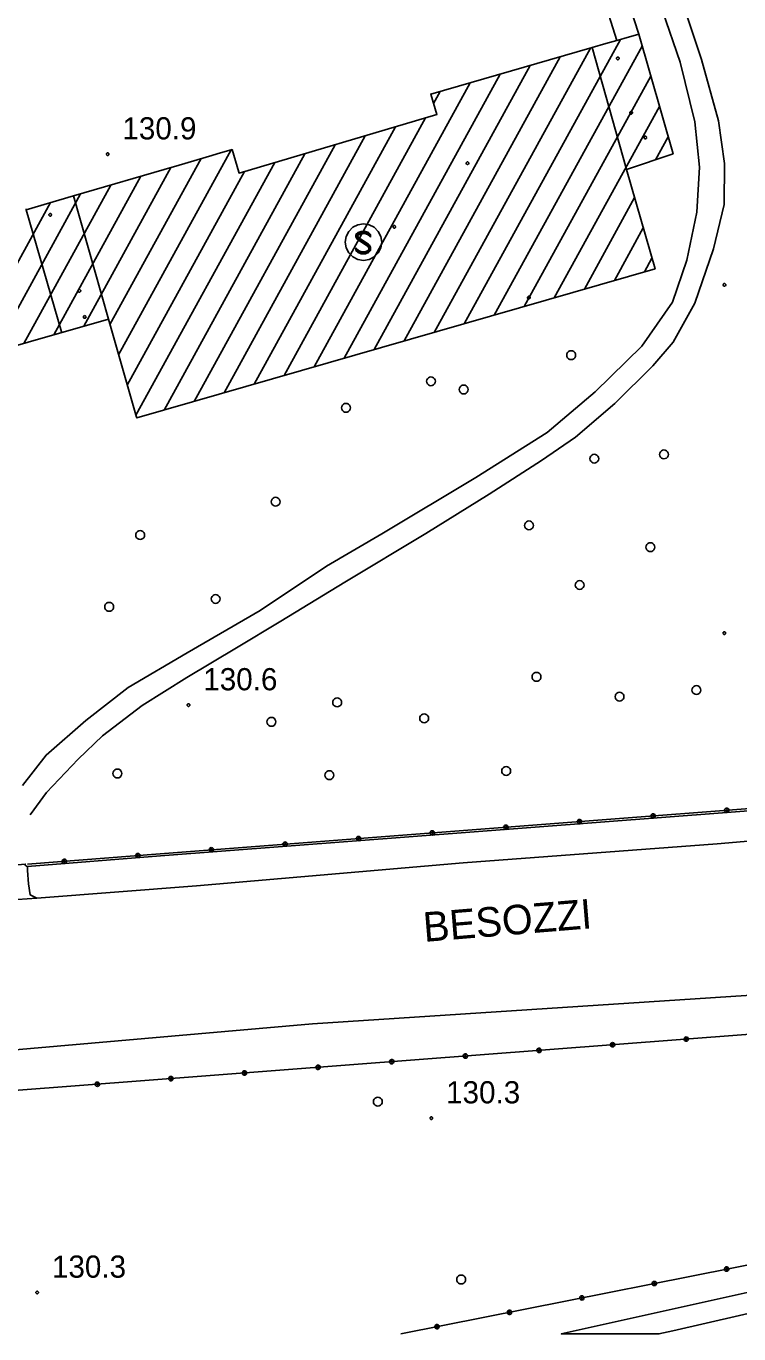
# Model space of a CAD drawing. Extents: x 513373 to 514978, y 5038576 to 5040180.
# Drawn here: x 513502.4 to 513550.7, y 5038580.1 to 5038668.6 of the extents above; entities that cross this region are included whole.
import ezdxf

# ---------------------------------------------------------------- set-up
doc = ezdxf.new("R2010")
doc.units = 0
for name, color, linetype in [('2010300', 7, 'Continuous'), ('3010204', 7, 'Continuous'), ('3030201', 7, 'Continuous'), ('B1211', 7, 'Continuous'), ('C1131', 7, 'Continuous'), ('C12211', 7, 'Continuous'), ('C2911', 7, 'Continuous'), ('CAMP_C12211', 7, 'Continuous'), ('Default', 7, 'Continuous'), ('F12107', 7, 'Continuous'), ('F12131', 7, 'Continuous'), ('F12132', 7, 'Continuous'), ('G4315', 7, 'Continuous'), ('TOP500', 7, 'Continuous'), ('TOP920', 7, 'Continuous')]:
    doc.layers.add(name, color=color, linetype=linetype)

# ---------------------------------------------------------------- blocks, each defined once
blk = doc.blocks.new('CAMP_2F84D089')
at = {"layer": 'CAMP_C12211'}
for p, q in [((49.808, -7.618), (60.382, 11.617)), ((47.775, -8.202), (58.347, 11.029)), ((51.841, -7.034), (61.849, 11.171)), ((43.709, -9.371), (54.279, 9.856)), ((45.742, -8.787), (56.313, 10.442)), ((41.676, -9.955), (52.245, 9.269)), ((53.874, -6.45), (62.437, 9.127)), ((39.643, -10.54), (50.21, 8.682)), ((47.729, 7.282), (48.176, 8.095)), ((55.907, -5.865), (63.024, 7.082)), ((37.61, -11.124), (47.19, 6.302)), ((35.577, -11.708), (45.146, 5.698)), ((31.511, -12.877), (41.059, 4.491)), ((33.544, -12.293), (43.103, 5.094)), ((62.756, 3.48), (63.612, 5.037)), ((25.809, -7.68), (31.984, 3.551)), ((26.397, -9.725), (34.023, 4.147)), ((29.478, -13.461), (39.015, 3.887)), ((24.042, -7.782), (29.945, 2.956)), ((26.985, -11.769), (34.928, 2.68)), ((27.573, -13.814), (36.972, 3.283)), ((22.009, -8.366), (27.906, 2.36)), ((17.943, -9.535), (23.827, 1.168)), ((19.976, -8.95), (25.866, 1.764)), ((57.94, -5.281), (61.345, 0.913)), ((15.91, -10.119), (21.788, 0.573)), ((59.973, -4.697), (61.932, -1.132)), ((62.005, -4.112), (62.519, -3.177))]:
    blk.add_line(p, q, dxfattribs=at)
blk = doc.blocks.new('03080200')
at = {"layer": 'Default'}
for p, q in [((-0.139, 0.046), (-0.146, 0)), ((-0.146, 0), (-0.139, -0.046)), ((-0.118, 0.086), (-0.139, 0.046)), ((-0.086, 0.118), (-0.118, 0.086)), ((-0.046, 0.139), (-0.086, 0.118)), ((0, 0.146), (-0.046, 0.139)), ((-0.042, 0.014), (-0.045, 0)), ((-0.045, 0), (-0.042, -0.014)), ((-0.036, 0.026), (-0.042, 0.014)), ((-0.026, 0.036), (-0.036, 0.026)), ((-0.014, 0.042), (-0.026, 0.036)), ((0, 0.045), (-0.014, 0.042)), ((0.046, 0.139), (0, 0.146)), ((0.014, 0.042), (0, 0.045)), ((0.026, 0.036), (0.014, 0.042)), ((0.036, 0.026), (0.026, 0.036)), ((0.042, 0.014), (0.036, 0.026)), ((0.045, 0), (0.042, 0.014)), ((0.042, -0.014), (0.045, 0)), ((0.086, 0.118), (0.046, 0.139)), ((0.118, 0.086), (0.086, 0.118)), ((0.139, 0.046), (0.118, 0.086)), ((0.146, 0), (0.139, 0.046)), ((0.139, -0.046), (0.146, 0)), ((-0.139, -0.046), (-0.118, -0.086)), ((-0.118, -0.086), (-0.086, -0.118)), ((-0.086, -0.118), (-0.046, -0.139)), ((-0.046, -0.139), (0, -0.146)), ((-0.042, -0.014), (-0.036, -0.026)), ((-0.036, -0.026), (-0.026, -0.036)), ((-0.026, -0.036), (-0.014, -0.042)), ((-0.014, -0.042), (0, -0.045)), ((0, -0.045), (0.014, -0.042)), ((0, -0.146), (0.046, -0.139)), ((0.014, -0.042), (0.026, -0.036)), ((0.026, -0.036), (0.036, -0.026)), ((0.036, -0.026), (0.042, -0.014)), ((0.046, -0.139), (0.086, -0.118)), ((0.086, -0.118), (0.118, -0.086)), ((0.118, -0.086), (0.139, -0.046))]:
    blk.add_line(p, q, dxfattribs=at)
blk = doc.blocks.new('08020400')
at = {"layer": 'Default'}
for p, q in [((-0.086, 0.028), (-0.09, 0)), ((-0.09, 0), (-0.086, -0.028)), ((-0.073, 0.053), (-0.086, 0.028)), ((-0.053, 0.073), (-0.073, 0.053)), ((-0.028, 0.086), (-0.053, 0.073)), ((0, 0.09), (-0.028, 0.086)), ((0.028, 0.086), (0, 0.09)), ((0.053, 0.073), (0.028, 0.086)), ((0.073, 0.053), (0.053, 0.073)), ((0.086, 0.028), (0.073, 0.053)), ((0.09, 0), (0.086, 0.028)), ((0.086, -0.028), (0.09, 0)), ((-0.086, -0.028), (-0.073, -0.053)), ((-0.073, -0.053), (-0.053, -0.073)), ((-0.053, -0.073), (-0.028, -0.086)), ((-0.028, -0.086), (0, -0.09)), ((0, -0.09), (0.028, -0.086)), ((0.028, -0.086), (0.053, -0.073)), ((0.053, -0.073), (0.073, -0.053)), ((0.073, -0.053), (0.086, -0.028))]:
    blk.add_line(p, q, dxfattribs=at)
blk = doc.blocks.new('NSIMB25')
at = {"layer": 'Default'}
for p, q in [((-0.086, 0.028), (-0.09, 0)), ((-0.09, 0), (-0.086, -0.028)), ((-0.073, 0.053), (-0.086, 0.028)), ((-0.053, 0.073), (-0.073, 0.053)), ((-0.028, 0.086), (-0.053, 0.073)), ((0, 0.09), (-0.028, 0.086)), ((0.028, 0.086), (0, 0.09)), ((0.053, 0.073), (0.028, 0.086)), ((0.073, 0.053), (0.053, 0.073)), ((0.086, 0.028), (0.073, 0.053)), ((0.09, 0), (0.086, 0.028)), ((0.086, -0.028), (0.09, 0)), ((-0.086, -0.028), (-0.073, -0.053)), ((-0.073, -0.053), (-0.053, -0.073)), ((-0.053, -0.073), (-0.028, -0.086)), ((-0.028, -0.086), (0, -0.09)), ((0, -0.09), (0.028, -0.086)), ((0.028, -0.086), (0.053, -0.073)), ((0.053, -0.073), (0.073, -0.053)), ((0.073, -0.053), (0.086, -0.028))]:
    blk.add_line(p, q, dxfattribs=at)
blk = doc.blocks.new('05010100')
at = {"layer": 'Default'}
for p, q in [((-0.143, 0.046), (-0.15, 0)), ((-0.15, 0), (-0.143, -0.046)), ((-0.121, 0.088), (-0.143, 0.046)), ((-0.088, 0.121), (-0.121, 0.088)), ((-0.046, 0.143), (-0.088, 0.121)), ((0, 0.15), (-0.046, 0.143)), ((0.046, 0.143), (0, 0.15)), ((0.088, 0.121), (0.046, 0.143)), ((0.121, 0.088), (0.088, 0.121)), ((0.143, 0.046), (0.121, 0.088)), ((0.15, 0), (0.143, 0.046)), ((0.143, -0.046), (0.15, 0)), ((-0.143, -0.046), (-0.121, -0.088)), ((-0.121, -0.088), (-0.088, -0.121)), ((-0.088, -0.121), (-0.046, -0.143)), ((-0.046, -0.143), (0, -0.15)), ((0, -0.15), (0.046, -0.143)), ((0.046, -0.143), (0.088, -0.121)), ((0.088, -0.121), (0.121, -0.088)), ((0.121, -0.088), (0.143, -0.046))]:
    blk.add_line(p, q, dxfattribs=at)
blk = doc.blocks.new('03030201')
at = {"layer": 'Default'}
for p, q in [((-0.728, 1.001), (-1.001, 0.728)), ((-0.382, 1.177), (-0.728, 1.001)), ((0, 1.237), (-0.382, 1.177)), ((0.382, 1.177), (0, 1.237)), ((0.728, 1.001), (0.382, 1.177)), ((1.001, 0.728), (0.728, 1.001)), ((-1.177, 0.382), (-1.238, 0)), ((-1.238, 0), (-1.177, -0.382)), ((-1.001, 0.728), (-1.177, 0.382)), ((-0.518, 0.508), (-0.368, 0.643)), ((-0.518, 0.358), (-0.518, 0.508)), ((-0.443, 0.223), (-0.518, 0.358)), ((-0.333, 0.584), (-0.451, 0.478)), ((-0.451, 0.478), (-0.451, 0.376)), ((-0.451, 0.376), (-0.389, 0.265)), ((-0.368, 0.148), (-0.443, 0.223)), ((-0.389, 0.265), (-0.326, 0.201)), ((-0.298, 0.526), (-0.383, 0.448)), ((-0.383, 0.448), (-0.383, 0.394)), ((-0.383, 0.394), (-0.335, 0.306)), ((-0.368, 0.643), (-0.158, 0.718)), ((0.148, -0.186), (-0.368, 0.148)), ((-0.335, 0.306), (-0.287, 0.257)), ((-0.147, 0.651), (-0.333, 0.584)), ((-0.326, 0.201), (0.183, -0.128)), ((-0.135, 0.583), (-0.298, 0.526)), ((-0.287, 0.257), (-0.18, 0.198)), ((-0.18, 0.198), (0.337, -0.137)), ((-0.158, 0.718), (0.127, 0.718)), ((0.115, 0.651), (-0.147, 0.651)), ((0.103, 0.583), (-0.135, 0.583)), ((0.266, 0.526), (0.103, 0.583)), ((0.301, 0.584), (0.115, 0.651)), ((0.127, 0.718), (0.337, 0.643)), ((0.487, 0.327), (0.266, 0.526)), ((0.487, 0.418), (0.301, 0.584)), ((0.337, 0.643), (0.487, 0.508)), ((0.487, 0.508), (0.487, 0.327)), ((1.177, 0.382), (1.001, 0.728)), ((1.238, 0), (1.177, 0.382)), ((1.177, -0.382), (1.238, 0)), ((-1.177, -0.382), (-1.001, -0.728)), ((-1.001, -0.728), (-0.728, -1.001)), ((-0.518, -0.39), (-0.298, -0.588)), ((-0.518, -0.572), (-0.518, -0.39)), ((-0.333, -0.647), (-0.518, -0.481)), ((-0.368, -0.707), (-0.518, -0.572)), ((-0.158, -0.782), (-0.368, -0.707)), ((-0.147, -0.714), (-0.333, -0.647)), ((-0.298, -0.588), (-0.135, -0.647)), ((0.127, -0.782), (-0.158, -0.782)), ((0.115, -0.714), (-0.147, -0.714)), ((-0.135, -0.647), (0.103, -0.647)), ((0.103, -0.647), (0.266, -0.588)), ((0.301, -0.647), (0.115, -0.714)), ((0.337, -0.707), (0.127, -0.782)), ((0.254, -0.245), (0.148, -0.186)), ((0.183, -0.128), (0.295, -0.191)), ((0.302, -0.293), (0.254, -0.245)), ((0.266, -0.588), (0.352, -0.512)), ((0.295, -0.191), (0.357, -0.253)), ((0.419, -0.542), (0.301, -0.647)), ((0.352, -0.382), (0.302, -0.293)), ((0.337, -0.137), (0.412, -0.212)), ((0.487, -0.572), (0.337, -0.707)), ((0.352, -0.512), (0.352, -0.382)), ((0.357, -0.253), (0.419, -0.364)), ((0.412, -0.212), (0.487, -0.347)), ((0.419, -0.364), (0.419, -0.542)), ((0.487, -0.347), (0.487, -0.572)), ((0.728, -1.001), (1.001, -0.728)), ((1.001, -0.728), (1.177, -0.382)), ((-0.728, -1.001), (-0.382, -1.177)), ((-0.382, -1.177), (0, -1.238)), ((0, -1.238), (0.382, -1.177)), ((0.382, -1.177), (0.728, -1.001))]:
    blk.add_line(p, q, dxfattribs=at)
blk = doc.blocks.new('A$C3704598A')
at = {"layer": '2010300'}
blk.add_lwpolyline([(165.65, -800.002), (186.154, -795.446), (186.667, -795.332), (187.178, -795.219)], dxfattribs=at)
at = {"layer": '3010204'}
for points in [[(130.78, -763.373), (132.923, -761.13), (134.586, -759.538), (137.271, -757.48), (140.294, -755.605), (143.656, -753.598), (146.655, -751.79), (150.994, -749.135), (156.469, -745.856), (160.764, -743.2), (164.309, -740.923), (166.605, -739.336), (169.269, -737.051), (171.844, -734.517), (173.213, -732.901), (174.681, -730.267), (175.954, -726.593), (176.68, -723.592), (176.702, -720.811), (176.296, -717.936), (175.153, -713.79), (173.012, -707.42)], [(171.782, -708.472), (172.512, -710.49), (173.705, -713.959), (174.69, -717.991), (175.004, -721.069), (174.821, -724.119), (174.14, -727.369), (173.19, -730.21), (171.108, -733.178), (167.941, -736.272), (164.686, -739.027), (159.868, -742.062), (153.485, -745.877), (149.737, -748.062), (145.259, -751.056), (140.307, -753.932), (136.309, -756.274), (133.443, -758.512), (130.755, -760.841), (129.156, -762.908)], [(168.448, -709.407), (169.416, -712.491)], [(169.896, -709.001), (170.888, -712.066)], [(130.78, -763.373), (129.681, -764.88)]]:
    blk.add_lwpolyline(points, dxfattribs=at)
at = {"layer": 'B1211'}
for points in [[(182.854, -779.395), (110.289, -784.942), (71.944, -788.357), (71.695, -785.89), (71.68, -785.737), (74.707, -785.49), (148.809, -779.036), (181.633, -776.874)], [(190.042, -765.652), (176.206, -766.841), (159.007, -768.13), (140.939, -769.683), (130.118, -770.52), (129.683, -770.31), (129.556, -769.565), (129.505, -768.659), (129.503, -768.536), (129.499, -768.38), (138.496, -767.667), (189.536, -763.755)]]:
    blk.add_lwpolyline(points, dxfattribs=at)
for points in [[(129.499, -768.38), (129.503, -768.536), (129.505, -768.659), (129.556, -769.565), (129.683, -770.31), (130.118, -770.52), (128.815, -770.62), (126.207, -770.822), (126.566, -770.204), (126.591, -769.326), (126.388, -768.62), (126.424, -768.6), (126.448, -768.577), (126.467, -768.547), (126.48, -768.508), (126.48, -768.461), (129.344, -768.218), (129.347, -768.247), (129.349, -768.267), (129.368, -768.312), (129.402, -768.35), (129.432, -768.367), (129.469, -768.378)], [(239.733, -784.162), (238.193, -784.525), (218.713, -789.182), (196.51, -794.439), (195.488, -794.673), (173.196, -799.794), (172.259, -800.002), (165.65, -800.002), (186.154, -795.446), (186.667, -795.332), (187.178, -795.219), (234.926, -783.811), (239.656, -782.696), (240.683, -782.453)]]:
    blk.add_lwpolyline(points, close=True, dxfattribs=at)
at = {"layer": 'C1131'}
for points in [[(170.068, -721.225), (170.039, -721.125), (167.729, -712.978), (168.669, -712.707), (169.408, -712.493), (169.881, -712.357), (170.888, -712.066), (173.213, -720.156)], [(170.068, -721.225), (171.998, -727.944), (136.894, -738.034), (136.879, -737.982), (134.971, -731.345), (132.618, -723.012), (139.462, -721.011), (139.54, -720.988), (140.996, -720.564), (141.976, -720.277), (142.351, -720.168), (143.357, -719.874), (143.81, -721.41), (143.828, -721.469), (157.221, -717.513), (156.812, -716.127), (166.721, -713.269), (167.729, -712.978), (170.039, -721.125)], [(134.971, -731.345), (133.964, -731.634), (131.815, -732.252), (131.8, -732.2), (129.413, -723.947), (131.612, -723.305), (132.618, -723.012)]]:
    blk.add_lwpolyline(points, close=True, dxfattribs=at)
blk.add_lwpolyline([(129.397, -723.891), (129.413, -723.947), (131.8, -732.2), (131.815, -732.252), (122.84, -734.831)], dxfattribs=at)
at = {"layer": 'C12211'}
blk.add_lwpolyline([(129.397, -723.891), (129.413, -723.947), (131.612, -723.305), (132.618, -723.012), (139.462, -721.011), (139.54, -720.988), (140.996, -720.564), (141.976, -720.277), (142.351, -720.168), (143.357, -719.874), (143.81, -721.41), (143.828, -721.469), (157.221, -717.513), (156.812, -716.127), (166.721, -713.269), (167.729, -712.978), (168.669, -712.707), (169.408, -712.493), (169.881, -712.357), (170.888, -712.066), (173.213, -720.156), (170.068, -721.225), (171.998, -727.944), (136.894, -738.034), (136.879, -737.982), (134.971, -731.345), (133.964, -731.634), (131.815, -732.252), (122.84, -734.831)], dxfattribs=at)
at = {"layer": 'C2911'}
for points in [[(129.493, -768.231), (138.486, -767.517), (158.144, -766.013), (189.264, -763.627), (189.631, -763.599), (190.369, -763.543), (197.35, -752.142), (188.981, -734.343), (179.304, -712.974), (176.303, -705.995)], [(71.944, -788.357), (110.289, -784.942), (182.854, -779.395)], [(154.78, -800.002), (185.721, -793.86), (186.751, -793.656)]]:
    blk.add_lwpolyline(points, dxfattribs=at)
at = {"layer": '3030201'}
blk.add_blockref('03030201', (152.25, -726.137), dxfattribs=at)
at = {"layer": 'C2911'}
for p, rotation in [((176.853, -764.579), 4.383950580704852), ((166.882, -765.343), 4.383950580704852), ((171.867, -764.961), 4.383950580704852), ((156.911, -766.107), 4.374192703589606), ((161.897, -765.725), 4.383950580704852), ((146.94, -766.87), 4.374192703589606), ((151.926, -766.489), 4.374192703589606), ((131.986, -768.033), 4.538595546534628), ((136.97, -767.637), 4.538595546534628), ((141.955, -767.252), 4.374192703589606), ((169.121, -780.444), 4.371974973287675), ((174.107, -780.063), 4.371974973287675), ((159.15, -781.207), 4.371974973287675), ((164.136, -780.826), 4.371974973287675), ((149.179, -781.969), 4.371974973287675), ((154.165, -781.588), 4.371974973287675), ((134.223, -783.113), 4.371974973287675), ((139.208, -782.731), 4.371974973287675), ((144.194, -782.35), 4.371974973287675), ((176.85, -795.621), 11.227944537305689), ((171.945, -796.595), 11.227944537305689), ((167.041, -797.568), 11.227944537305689), ((162.137, -798.542), 11.227944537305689), ((157.232, -799.515), 11.227944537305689)]:
    blk.add_blockref('03080200', p, dxfattribs=dict(at, rotation=rotation))
at = {"layer": 'CAMP_C12211'}
blk.add_blockref('CAMP_2F84D089', (109.269, -724.04), dxfattribs=at)
at = {"layer": 'F12107'}
for p in [(134.922, -720.188), (176.696, -729.032), (176.687, -752.59), (140.401, -757.46), (156.845, -785.408), (130.151, -797.203)]:
    blk.add_blockref('08020400', p, dxfattribs=at)
at = {"layer": 'F12131'}
for p in [(170.378, -717.384), (154.341, -725.103), (133.014, -729.436)]:
    blk.add_blockref('NSIMB25', p, dxfattribs=at)
at = {"layer": 'F12132'}
for p in [(169.479, -713.708), (171.34, -719.064), (159.298, -720.801), (131.036, -724.288), (163.451, -729.89), (133.372, -731.203)]:
    blk.add_blockref('NSIMB25', p, dxfattribs=at)
at = {"layer": 'G4315', "xscale": 2, "yscale": 2}
for p in [(166.314, -733.788), (156.82, -735.553), (159.036, -736.113), (151.063, -737.349), (167.883, -740.789), (172.599, -740.502), (146.299, -743.703), (137.125, -745.958), (163.459, -745.304), (171.68, -746.778), (166.892, -749.34), (142.237, -750.279), (135.027, -750.817), (163.971, -755.547), (174.798, -756.446), (150.468, -757.28), (169.594, -756.892), (156.364, -758.356), (146.015, -758.598), (161.915, -761.922), (135.586, -762.089), (149.941, -762.205), (153.222, -784.293), (158.868, -796.323)]:
    blk.add_blockref('05010100', p, dxfattribs=at)
at = {"layer": 'TOP500'}
blk.add_text('BESOZZI', height=2, rotation=4.6717, dxfattribs=at).set_placement((156.372, -773.488))
at = {"layer": 'TOP920'}
for s, p in [('130.9', (135.922, -719.188)), ('130.6', (141.401, -756.46)), ('130.3', (157.845, -784.408)), ('130.3', (131.151, -796.203))]:
    blk.add_text(s, height=1.5, dxfattribs=at).set_placement(p)

msp = doc.modelspace()

# ---------------------------------------------------------------- block references
at = {"layer": 'Default'}
msp.add_blockref('A$C3704598A', (513373.046, 5039380.14), dxfattribs=at)

doc.saveas('drawing.dxf')
